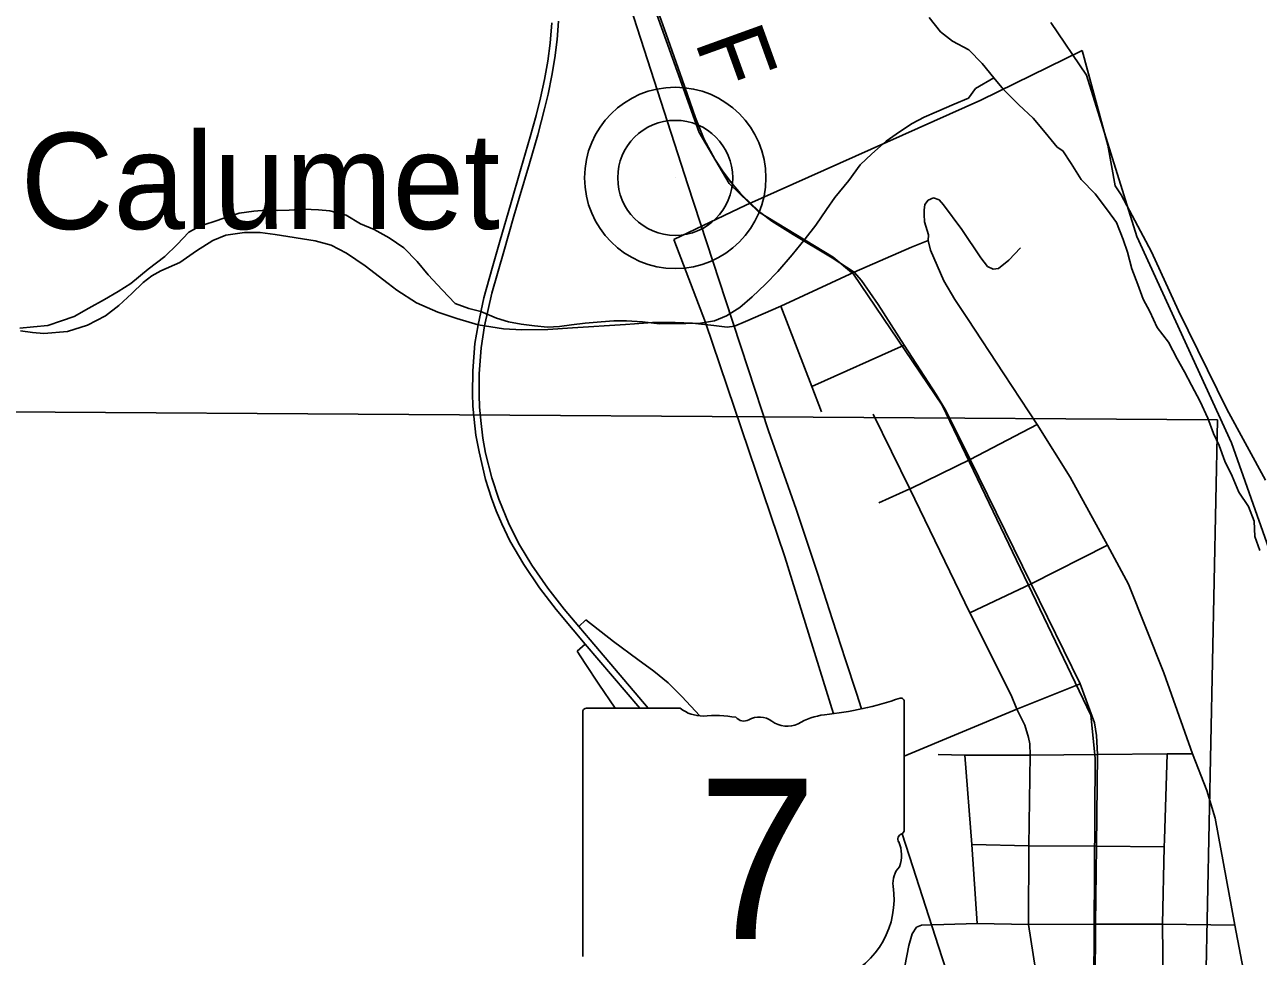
# Model space of a CAD drawing. Extents: x 0 to 34, y 0 to 22.
# Drawn here: x 7.482 to 8.494, y 19.658 to 20.423 of the extents above; entities that cross this region are included whole.
import ezdxf

# ---------------------------------------------------------------- set-up
doc = ezdxf.new("R2010")
doc.units = 0
for name, color, linetype in [('Default', 7, 'Continuous'), ('GM_X_City_Street', 7, 'Continuous'), ('GM_X_Corporation', 7, 'Continuous'), ('GM_X_County_Road', 7, 'Continuous'), ('GM_X_County_Road_Text', 7, 'Continuous'), ('GM_X_Interchange_Ramps', 7, 'Continuous'), ('GM_X_Major_River', 7, 'Continuous'), ('GM_X_Minor_River', 7, 'Continuous'), ('GM_X_Rail_Line', 7, 'Continuous'), ('GM_X_Section', 7, 'Continuous'), ('GM_X_State_Route', 7, 'Continuous'), ('GM_X_State_Shield', 7, 'Continuous'), ('GM_X_Unincorporated', 7, 'Continuous'), ('GM_X_Unincorporated_Location', 7, 'Continuous'), ('GM_X_Unincorporated_Text', 7, 'Continuous'), ('SH_Cut_Line', 7, 'Continuous')]:
    doc.layers.add(name, color=color, linetype=linetype)

msp = doc.modelspace()

# ---------------------------------------------------------------- linework, layer by layer
at = {"layer": 'Default'}
for p, q in [((8.3529, 20.3814), (8.3237, 20.4245)), ((8.3941, 20.2491), (8.3529, 20.3814)), ((8.4717, 20.0797), (8.3941, 20.2491)), ((8.5259, 19.9261), (8.4717, 20.0797))]:
    msp.add_line(p, q, dxfattribs=at)
at = {"layer": 'GM_X_City_Street'}
for p, q in [((8.2196, 20.2705), (8.2203, 20.2752)), ((8.2203, 20.2752), (8.223, 20.2789)), ((8.223, 20.2789), (8.2274, 20.2807)), ((8.2274, 20.2807), (8.2321, 20.2791)), ((8.2321, 20.2791), (8.2357, 20.2749)), ((8.2357, 20.2749), (8.2506, 20.2546)), ((8.2196, 20.2671), (8.2196, 20.2705)), ((8.2201, 20.2609), (8.2196, 20.2671)), ((8.2232, 20.2504), (8.2201, 20.2609)), ((8.2506, 20.2546), (8.2662, 20.2314)), ((8.2094, 20.2402), (8.223, 20.2456)), ((8.223, 20.2456), (8.2232, 20.2504)), ((8.225, 20.2379), (8.223, 20.2456)), ((8.1622, 20.2196), (8.2094, 20.2402)), ((8.2358, 20.2126), (8.225, 20.2379)), ((8.2662, 20.2314), (8.2717, 20.2244)), ((8.2892, 20.2296), (8.2986, 20.2398)), ((8.2717, 20.2244), (8.2764, 20.2223)), ((8.2764, 20.2223), (8.2808, 20.2228)), ((8.2808, 20.2228), (8.2892, 20.2296)), ((8.2449, 20.1973), (8.2358, 20.2126)), ((8.1276, 20.1259), (8.1021, 20.1918)), ((8.2552, 20.1816), (8.2449, 20.1973)), ((8.2851, 20.1362), (8.2552, 20.1816)), ((8.1276, 20.1259), (8.2033, 20.1598)), ((8.3123, 20.0947), (8.2851, 20.1362)), ((8.1356, 20.1051), (8.1276, 20.1259)), ((8.2079, 20.0419), (8.178, 20.1031)), ((8.2575, 20.0661), (8.3123, 20.0947)), ((8.3394, 20.0515), (8.3123, 20.0947)), ((8.2088, 20.0423), (8.2575, 20.0661)), ((8.37, 19.9956), (8.3394, 20.0515)), ((8.1824, 20.0305), (8.2079, 20.0419)), ((8.2079, 20.0419), (8.2088, 20.0423)), ((8.2573, 19.9403), (8.2079, 20.0419)), ((8.3076, 19.964), (8.37, 19.9956)), ((8.3874, 19.9636), (8.37, 19.9956)), ((8.2573, 19.9403), (8.3076, 19.964)), ((8.4163, 19.8909), (8.3874, 19.9636)), ((8.291, 19.8725), (8.2573, 19.9403)), ((8.4398, 19.8245), (8.4163, 19.8909)), ((8.2958, 19.8611), (8.291, 19.8725)), ((8.3022, 19.8479), (8.2958, 19.8611)), ((8.3053, 19.8378), (8.3022, 19.8479)), ((8.3065, 19.8328), (8.3053, 19.8378)), ((8.3067, 19.8234), (8.3065, 19.8328)), ((8.2312, 19.824), (8.2531, 19.8235)), ((8.2589, 19.7501), (8.2531, 19.8235)), ((8.2531, 19.8235), (8.3067, 19.8234)), ((8.3056, 19.7489), (8.3067, 19.8234)), ((8.3067, 19.8234), (8.3618, 19.8239)), ((8.3618, 19.8239), (8.419, 19.8245)), ((8.4168, 19.7541), (8.419, 19.8245)), ((8.419, 19.8245), (8.4398, 19.8245)), ((8.4515, 19.7945), (8.4398, 19.8245)), ((8.4584, 19.7717), (8.4515, 19.7945)), ((8.4746, 19.6839), (8.4584, 19.7717)), ((8.2631, 19.6853), (8.2589, 19.7501)), ((8.2589, 19.7501), (8.3056, 19.7489)), ((8.3053, 19.6845), (8.3056, 19.7489)), ((8.3056, 19.7489), (8.361, 19.7486)), ((8.361, 19.7486), (8.4166, 19.7481)), ((8.4151, 19.6846), (8.4166, 19.7481)), ((8.4166, 19.7481), (8.4168, 19.7541)), ((8.2175, 19.684), (8.2631, 19.6853)), ((8.2631, 19.6853), (8.3053, 19.6845)), ((8.2071, 19.6673), (8.2099, 19.6769)), ((8.2099, 19.6769), (8.2133, 19.6821)), ((8.2133, 19.6821), (8.2175, 19.684)), ((8.3053, 19.6845), (8.3603, 19.6846)), ((8.3212, 19.5833), (8.3053, 19.6845)), ((8.4151, 19.6846), (8.4746, 19.6839)), ((8.4938, 19.5823), (8.4746, 19.6839)), ((8.2039, 19.6503), (8.2071, 19.6673))]:
    msp.add_line(p, q, dxfattribs=at)
at = {"layer": 'GM_X_Corporation'}
for p, q in [((8.2662, 20.3608), (8.3492, 20.4017)), ((8.3492, 20.4017), (8.3704, 20.3238)), ((8.0734, 20.2747), (8.2662, 20.3608)), ((8.3704, 20.3238), (8.3764, 20.2906)), ((8.3764, 20.2906), (8.3812, 20.2831)), ((8.3812, 20.2831), (8.4062, 20.2365)), ((8.0144, 20.2466), (8.0734, 20.2747)), ((8.0402, 20.1783), (8.0144, 20.2466)), ((8.4062, 20.2365), (8.4283, 20.1879)), ((8.4283, 20.1879), (8.4681, 20.1072)), ((8.1055, 19.9861), (8.0402, 20.1783)), ((8.4681, 20.1072), (8.4996, 20.049)), ((8.1453, 19.8574), (8.1055, 19.9861))]:
    msp.add_line(p, q, dxfattribs=at)
at = {"layer": 'GM_X_County_Road'}
for p, q in [((8.008, 20.4149), (7.9943, 20.4538)), ((8.0211, 20.3779), (8.008, 20.4149)), ((8.032, 20.3465), (8.0211, 20.3779)), ((8.0392, 20.3286), (8.032, 20.3465)), ((8.0481, 20.3125), (8.0392, 20.3286)), ((8.0543, 20.3028), (8.0481, 20.3125)), ((8.0615, 20.2934), (8.0543, 20.3028)), ((8.0689, 20.2844), (8.0615, 20.2934)), ((8.0788, 20.2746), (8.0689, 20.2844)), ((8.0856, 20.2683), (8.0788, 20.2746)), ((8.0947, 20.2617), (8.0856, 20.2683)), ((7.6469, 20.2501), (7.6622, 20.2524)), ((7.6622, 20.2524), (7.675, 20.2523)), ((7.675, 20.2523), (7.6872, 20.2507)), ((8.1122, 20.2506), (8.0947, 20.2617)), ((7.6228, 20.2371), (7.6361, 20.2457)), ((7.6361, 20.2457), (7.6469, 20.2501)), ((7.6872, 20.2507), (7.72, 20.2455)), ((7.72, 20.2455), (7.7331, 20.2419)), ((7.7331, 20.2419), (7.7457, 20.2354)), ((8.1443, 20.2316), (8.1122, 20.2506)), ((7.609, 20.2277), (7.6228, 20.2371)), ((7.7457, 20.2354), (7.7611, 20.2249)), ((8.1622, 20.2196), (8.1443, 20.2316)), ((7.5934, 20.2208), (7.609, 20.2277)), ((7.7611, 20.2249), (7.78, 20.2104)), ((7.5696, 20.2021), (7.579, 20.2113)), ((7.579, 20.2113), (7.586, 20.2167)), ((7.586, 20.2167), (7.5934, 20.2208)), ((8.1021, 20.1918), (8.1622, 20.2196)), ((8.1682, 20.213), (8.1622, 20.2196)), ((8.1819, 20.1931), (8.1682, 20.213)), ((7.5591, 20.1924), (7.5696, 20.2021)), ((7.78, 20.2104), (7.7871, 20.2049)), ((7.7871, 20.2049), (7.8031, 20.1946)), ((7.5481, 20.184), (7.5591, 20.1924)), ((7.8031, 20.1946), (7.8207, 20.1869)), ((8.0731, 20.1792), (8.1021, 20.1918)), ((8.2033, 20.1598), (8.1819, 20.1931)), ((7.5334, 20.1762), (7.5481, 20.184)), ((7.8207, 20.1869), (7.8364, 20.1816)), ((7.8364, 20.1816), (7.8537, 20.1766)), ((7.4784, 20.1716), (7.4881, 20.1701)), ((7.4974, 20.1693), (7.5168, 20.171)), ((7.5168, 20.171), (7.5334, 20.1762)), ((7.8537, 20.1766), (7.8591, 20.1756)), ((7.8591, 20.1756), (7.8745, 20.1732)), ((7.8745, 20.1732), (7.8895, 20.1723)), ((7.8895, 20.1723), (7.9111, 20.1727)), ((7.9111, 20.1727), (7.9313, 20.1741)), ((7.9313, 20.1741), (7.9746, 20.1769)), ((7.9746, 20.1769), (7.9967, 20.1783)), ((7.9967, 20.1783), (8.0114, 20.1784)), ((8.0114, 20.1784), (8.0155, 20.1783)), ((8.0155, 20.1783), (8.0297, 20.178)), ((8.0297, 20.178), (8.0471, 20.1759)), ((8.0471, 20.1759), (8.058, 20.1745)), ((8.058, 20.1745), (8.0641, 20.1753)), ((8.0641, 20.1753), (8.0731, 20.1792)), ((7.4881, 20.1701), (7.4974, 20.1693)), ((8.2296, 20.1193), (8.2033, 20.1598)), ((8.2374, 20.1063), (8.2296, 20.1193)), ((8.2452, 20.091), (8.2374, 20.1063)), ((8.2575, 20.0661), (8.2452, 20.091)), ((8.3076, 19.964), (8.2575, 20.0661)), ((8.3477, 19.8819), (8.3076, 19.964)), ((8.2958, 19.8611), (8.3477, 19.8819)), ((8.3555, 19.8604), (8.3477, 19.8819)), ((8.2034, 19.8226), (8.2958, 19.8611)), ((8.3594, 19.8499), (8.3555, 19.8604)), ((8.361, 19.8396), (8.3594, 19.8499)), ((8.3618, 19.8239), (8.361, 19.8396)), ((8.361, 19.7486), (8.3618, 19.8239)), ((8.3603, 19.6846), (8.361, 19.7486)), ((8.3603, 19.6846), (8.3594, 19.5828)), ((8.4151, 19.6846), (8.3603, 19.6846)), ((8.4167, 19.5823), (8.4151, 19.6846))]:
    msp.add_line(p, q, dxfattribs=at)
at = {"layer": 'GM_X_Interchange_Ramps'}
for p, q in [((7.9421, 19.9345), (7.9363, 19.9289)), ((7.9648, 19.9167), (7.9421, 19.9345)), ((7.9417, 19.9145), (7.9349, 19.9086)), ((7.9349, 19.9086), (7.9416, 19.8985)), ((7.9848, 19.902), (7.9648, 19.9167)), ((7.9416, 19.8985), (7.9529, 19.8817)), ((7.9979, 19.8922), (7.9848, 19.902)), ((8.0096, 19.8827), (7.9979, 19.8922)), ((7.9529, 19.8817), (7.9663, 19.8619)), ((8.0212, 19.8712), (8.0096, 19.8827)), ((8.0357, 19.8556), (8.021, 19.8714))]:
    msp.add_line(p, q, dxfattribs=at)
at = {"layer": 'GM_X_Major_River'}
for p, q in [((8.2237, 20.4287), (8.233, 20.4168)), ((8.233, 20.4168), (8.243, 20.4094)), ((8.243, 20.4094), (8.2564, 20.4021)), ((8.2564, 20.4021), (8.2672, 20.3909)), ((8.2672, 20.3909), (8.2769, 20.3793)), ((8.2769, 20.3793), (8.2847, 20.3696)), ((8.2847, 20.3696), (8.2974, 20.3569)), ((8.2974, 20.3569), (8.309, 20.3462)), ((8.309, 20.3462), (8.3191, 20.3342)), ((8.3191, 20.3342), (8.3288, 20.3222)), ((8.3288, 20.3222), (8.3334, 20.3193)), ((8.3334, 20.3193), (8.3404, 20.3088)), ((8.3404, 20.3088), (8.3486, 20.2957)), ((8.3486, 20.2957), (8.3599, 20.2841)), ((8.3599, 20.2841), (8.37, 20.2707)), ((8.37, 20.2707), (8.3774, 20.2606)), ((8.3774, 20.2606), (8.3829, 20.2466)), ((8.3829, 20.2466), (8.3865, 20.2361)), ((8.3865, 20.2361), (8.3902, 20.2225)), ((8.3902, 20.2225), (8.395, 20.2097)), ((8.395, 20.2097), (8.3994, 20.1976)), ((8.3994, 20.1976), (8.4049, 20.1875)), ((8.4049, 20.1875), (8.4109, 20.1743)), ((8.4109, 20.1743), (8.4202, 20.1624)), ((8.4202, 20.1624), (8.4273, 20.1485)), ((8.4273, 20.1485), (8.4332, 20.138)), ((8.4332, 20.138), (8.439, 20.1271)), ((8.439, 20.1271), (8.4461, 20.1136)), ((8.4461, 20.1136), (8.4525, 20.1)), ((8.4525, 20.1), (8.4572, 20.0872)), ((8.4572, 20.0872), (8.4616, 20.0774)), ((8.4616, 20.0774), (8.4664, 20.0646)), ((8.4664, 20.0646), (8.4723, 20.0522)), ((8.4723, 20.0522), (8.4779, 20.0391)), ((8.4779, 20.0391), (8.4857, 20.0274)), ((8.4857, 20.0274), (8.4905, 20.0154)), ((8.4905, 20.0154), (8.4911, 20.0029)), ((8.4911, 20.0029), (8.4951, 19.9912))]:
    msp.add_line(p, q, dxfattribs=at)
at = {"layer": 'GM_X_Minor_River'}
for p, q in [((8.2618, 20.3703), (8.2769, 20.3793)), ((8.2618, 20.3703), (8.256, 20.3626)), ((8.2444, 20.3577), (8.2298, 20.3512)), ((8.256, 20.3626), (8.2444, 20.3577)), ((8.2196, 20.3468), (8.2099, 20.3416)), ((8.2298, 20.3512), (8.2196, 20.3468)), ((8.1994, 20.3348), (8.1886, 20.3273)), ((8.2099, 20.3416), (8.1994, 20.3348)), ((8.1886, 20.3273), (8.1767, 20.3167)), ((8.1767, 20.3167), (8.1671, 20.3077)), ((8.1671, 20.3077), (8.1579, 20.2949)), ((8.1579, 20.2949), (8.1465, 20.2809)), ((8.1465, 20.2809), (8.1396, 20.2712)), ((7.6469, 20.2647), (7.6363, 20.261)), ((7.6578, 20.2681), (7.6469, 20.2647)), ((7.6699, 20.2699), (7.6578, 20.2681)), ((7.6798, 20.2706), (7.6699, 20.2699)), ((7.6893, 20.2704), (7.6798, 20.2706)), ((7.6988, 20.2707), (7.6893, 20.2704)), ((7.7109, 20.2714), (7.6988, 20.2707)), ((7.7227, 20.271), (7.7109, 20.2714)), ((7.7322, 20.2701), (7.7227, 20.271)), ((7.7456, 20.2666), (7.7322, 20.2701)), ((7.7572, 20.2593), (7.7456, 20.2666)), ((8.1396, 20.2712), (8.1308, 20.2584)), ((7.6164, 20.2525), (7.6068, 20.2423)), ((7.6261, 20.2577), (7.6164, 20.2525)), ((7.6363, 20.261), (7.6261, 20.2577)), ((7.7684, 20.2547), (7.7572, 20.2593)), ((7.7807, 20.2478), (7.7684, 20.2547)), ((8.1308, 20.2584), (8.122, 20.2472)), ((7.6068, 20.2423), (7.5968, 20.2326)), ((7.7927, 20.2398), (7.7807, 20.2478)), ((8.122, 20.2472), (8.1113, 20.2339)), ((7.5968, 20.2326), (7.583, 20.2223)), ((7.8037, 20.2286), (7.7927, 20.2398)), ((8.1113, 20.2339), (8.0996, 20.2203)), ((7.583, 20.2223), (7.5689, 20.2105)), ((7.8127, 20.2175), (7.8037, 20.2286)), ((7.8244, 20.2052), (7.8127, 20.2175)), ((8.0996, 20.2203), (8.0896, 20.2098)), ((7.5585, 20.2038), (7.5472, 20.1974)), ((7.5689, 20.2105), (7.5585, 20.2038)), ((7.835, 20.1941), (7.8244, 20.2052)), ((8.0896, 20.2098), (8.0785, 20.1996)), ((7.5472, 20.1974), (7.5345, 20.1902)), ((7.8461, 20.1899), (7.835, 20.1941)), ((8.0785, 20.1996), (8.0684, 20.1906)), ((7.5225, 20.1834), (7.512, 20.1797)), ((7.5345, 20.1902), (7.5225, 20.1834)), ((7.8561, 20.1875), (7.8461, 20.1899)), ((7.8688, 20.1821), (7.8561, 20.1875)), ((7.8787, 20.179), (7.8688, 20.1821)), ((8.0576, 20.1838), (8.0478, 20.1797)), ((8.0684, 20.1906), (8.0576, 20.1838)), ((7.4889, 20.1749), (7.4779, 20.1738)), ((7.5007, 20.1759), (7.4889, 20.1749)), ((7.512, 20.1797), (7.5007, 20.1759)), ((7.8891, 20.177), (7.8787, 20.179)), ((7.9001, 20.1757), (7.8891, 20.177)), ((7.9108, 20.1745), (7.9001, 20.1757)), ((7.9206, 20.1751), (7.9108, 20.1745)), ((7.9305, 20.1766), (7.9206, 20.1751)), ((7.9415, 20.178), (7.9305, 20.1766)), ((7.9547, 20.1791), (7.9415, 20.178)), ((7.965, 20.1798), (7.9547, 20.1791)), ((7.9756, 20.1797), (7.965, 20.1798)), ((7.9886, 20.1789), (7.9756, 20.1797)), ((8.0027, 20.1774), (7.9886, 20.1789)), ((8.0243, 20.1776), (8.0027, 20.1774)), ((8.0361, 20.1779), (8.0243, 20.1776)), ((8.0478, 20.1797), (8.0361, 20.1779))]:
    msp.add_line(p, q, dxfattribs=at)
at = {"layer": 'GM_X_Rail_Line'}
for p, q in [((7.9664, 20.5265), (8.035, 20.3342)), ((7.9983, 20.3771), (7.965, 20.4793)), ((8.0259, 20.2913), (7.9983, 20.3771)), ((8.035, 20.3342), (8.0598, 20.2924)), ((8.0598, 20.2924), (8.0838, 20.2692)), ((8.0566, 20.1971), (8.0259, 20.2913)), ((8.0838, 20.2692), (8.1451, 20.2321)), ((8.1451, 20.2321), (8.1616, 20.2181)), ((8.1616, 20.2181), (8.2344, 20.1106)), ((8.0752, 20.1403), (8.0566, 20.1971)), ((8.0921, 20.0895), (8.0752, 20.1403)), ((8.2344, 20.1106), (8.3564, 19.8562)), ((8.1147, 20.0252), (8.0921, 20.0895)), ((8.1321, 19.9728), (8.1147, 20.0252)), ((8.1445, 19.9344), (8.1321, 19.9728)), ((8.1552, 19.9015), (8.1445, 19.9344)), ((8.1641, 19.8743), (8.1552, 19.9015)), ((8.1684, 19.8614), (8.1641, 19.8743)), ((8.3564, 19.8562), (8.36, 19.8208)), ((8.36, 19.8208), (8.3573, 19.356)), ((8.2104, 19.7317), (8.2016, 19.7589)), ((8.2315, 19.6665), (8.2104, 19.7317)), ((8.2488, 19.6131), (8.2315, 19.6665))]:
    msp.add_line(p, q, dxfattribs=at)
at = {"layer": 'GM_X_Section'}
for p, q in [((7.4653, 20.105), (8.4603, 20.0986)), ((8.4603, 20.0986), (8.4398, 19.0954))]:
    msp.add_line(p, q, dxfattribs=at)
at = {"layer": 'GM_X_State_Route'}
for p, q in [((7.9129, 20.4077), (7.9143, 20.4242)), ((7.9185, 20.4107), (7.9197, 20.4258)), ((7.911, 20.393), (7.9129, 20.4077)), ((7.9166, 20.3955), (7.9185, 20.4107)), ((7.9143, 20.381), (7.9166, 20.3955)), ((7.9082, 20.3779), (7.911, 20.393)), ((7.905, 20.3629), (7.9082, 20.3779)), ((7.9113, 20.3659), (7.9143, 20.381)), ((7.9013, 20.3482), (7.905, 20.3629)), ((7.9083, 20.3538), (7.9113, 20.3659)), ((7.9028, 20.3325), (7.9083, 20.3538)), ((7.8966, 20.3308), (7.9013, 20.3482)), ((7.8889, 20.3045), (7.8966, 20.3308)), ((7.896, 20.3088), (7.9028, 20.3325)), ((7.8803, 20.2751), (7.8889, 20.3045)), ((7.8875, 20.2805), (7.896, 20.3088)), ((7.8718, 20.246), (7.8803, 20.2751)), ((7.8831, 20.2656), (7.8875, 20.2805)), ((7.8748, 20.2367), (7.8831, 20.2656)), ((7.8653, 20.2231), (7.8718, 20.246)), ((7.8651, 20.2024), (7.8748, 20.2367)), ((7.8584, 20.1986), (7.8653, 20.2231)), ((7.8591, 20.1756), (7.8651, 20.2024)), ((7.8537, 20.1766), (7.8584, 20.1986)), ((7.8511, 20.1613), (7.8537, 20.1766)), ((7.8577, 20.1667), (7.8591, 20.1756)), ((7.8495, 20.1387), (7.8511, 20.1613)), ((7.8563, 20.1577), (7.8577, 20.1667)), ((7.8546, 20.1364), (7.8563, 20.1577)), ((7.8492, 20.1199), (7.8495, 20.1387)), ((7.8546, 20.1189), (7.8546, 20.1364)), ((7.8494, 20.1101), (7.8492, 20.1199)), ((7.8505, 20.0989), (7.8494, 20.1101)), ((7.8548, 20.1091), (7.8546, 20.1189)), ((7.8559, 20.0979), (7.8548, 20.1091)), ((7.852, 20.0859), (7.8505, 20.0989)), ((7.8577, 20.0836), (7.8559, 20.0979)), ((7.8545, 20.0723), (7.852, 20.0859)), ((7.8599, 20.0713), (7.8577, 20.0836)), ((7.8599, 20.0496), (7.8545, 20.0723)), ((7.8651, 20.0509), (7.8599, 20.0713)), ((7.8648, 20.0344), (7.8599, 20.0496)), ((7.8708, 20.0334), (7.8651, 20.0509)), ((7.8686, 20.024), (7.8648, 20.0344)), ((7.8792, 20.0127), (7.8708, 20.0334)), ((7.8732, 20.0133), (7.8686, 20.024)), ((7.8799, 19.9993), (7.8732, 20.0133)), ((7.8876, 19.9961), (7.8792, 20.0127)), ((7.8913, 19.9797), (7.8799, 19.9993)), ((7.8979, 19.9792), (7.8876, 19.9961)), ((7.9042, 19.9608), (7.8913, 19.9797)), ((7.911, 19.9604), (7.8979, 19.9792)), ((7.9179, 19.943), (7.9042, 19.9608)), ((7.9245, 19.9431), (7.911, 19.9604)), ((7.9317, 19.9261), (7.9179, 19.943)), ((7.9363, 19.9289), (7.9245, 19.9431)), ((7.9456, 19.9179), (7.9363, 19.9289)), ((7.9417, 19.9145), (7.9317, 19.9261)), ((7.9933, 19.8619), (7.9456, 19.9179)), ((7.9864, 19.8619), (7.9417, 19.9145))]:
    msp.add_line(p, q, dxfattribs=at)
at = {"layer": 'GM_X_State_Shield'}
for p, q in [((7.9397, 19.8584), (7.9397, 19.6583)), ((8.0195, 19.8619), (7.9423, 19.8619)), ((8.2034, 19.7621), (8.2034, 19.8668)), ((8.2033, 19.7622), (8.2034, 19.7621))]:
    msp.add_line(p, q, dxfattribs=at)
for centre, radius, start, end in [((8.1095, 20.1347), 0.2796, 275.8445, 288.9065), ((8.2005, 19.8673), 0.00294, 351.8621, 97.738), ((7.9427, 19.8589), 0.00305, 98.1301, 188.1301), ((8.0379, 19.8851), 0.0296, 231.6195, 271.1119), ((8.0477, 19.7495), 0.1064, 80.4867, 94.9883), ((8.0719, 19.8599), 0.00855, 219.7921, 297.1024), ((8.0844, 19.8368), 0.0178, 54.4667, 119.1411), ((8.1074, 19.8685), 0.0214, 233.8562, 294.8282), ((8.1451, 19.8007), 0.0563, 97.3462, 120.7689), ((8.2027, 19.7545), 0.00454, 107.944, 210.337), ((8.2002, 19.7617), 0.00314, 289.6038, 7.7341), ((8.1738, 19.7412), 0.0273, 340.033, 23.6496), ((8.2139, 19.7183), 0.0198, 136.8065, 186.9296), ((8.1251, 19.705), 0.0699, 292.3089, 8.9858)]:
    msp.add_arc(centre, radius, start, end, dxfattribs=at)
at = {"layer": 'GM_X_Unincorporated'}
for radius in [0.0744, 0.0472]:
    msp.add_circle((8.0155, 20.2971), radius, dxfattribs=at)
at = {"layer": 'GM_X_Unincorporated_Location'}
msp.add_line((8.0155, 20.2971), (8.0155, 20.2971), dxfattribs=at)
at = {"layer": 'SH_Cut_Line'}
for p, q in [((8.3529, 20.3814), (8.3237, 20.4245)), ((8.3941, 20.2491), (8.3529, 20.3814)), ((8.4717, 20.0797), (8.3941, 20.2491)), ((8.5259, 19.9261), (8.4717, 20.0797))]:
    msp.add_line(p, q, dxfattribs=at)

# ---------------------------------------------------------------- texts
at = {"layer": 'GM_X_County_Road_Text'}
msp.add_text('F', height=0.0568, rotation=289.876, dxfattribs=at).set_placement((8.0311, 20.4092))
at = {"layer": 'GM_X_State_Shield'}
msp.add_text('7', height=0.1318, dxfattribs=at).set_placement((8.0338, 19.6724))
at = {"layer": 'GM_X_Unincorporated_Text'}
msp.add_text('Calumet', height=0.07898, rotation=0, dxfattribs=at).set_placement((7.4784, 20.2551))

doc.saveas('drawing.dxf')
